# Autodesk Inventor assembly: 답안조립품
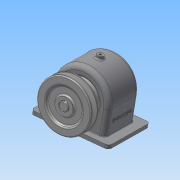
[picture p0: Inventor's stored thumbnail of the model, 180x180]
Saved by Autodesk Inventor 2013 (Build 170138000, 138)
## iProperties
Created: 2015-09
Part Number: 답안조립품
Document SubType Name: Assembly
Designer: ST3
Author: ST3
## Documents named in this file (14)
- C:\Users\ST3\Desktop\450907V1005\답안조립품.iam
- C:\Users\ST3\Desktop\450907V1005\V-벨트풀리.ipt
- C:\Users\ST3\Desktop\450907V1005\뒤커버.ipt
- C:\Users\ST3\Desktop\450907V1005\멈춤나사 - M4x10.ipt
- C:\Users\ST3\Desktop\450907V1005\베어링 6203.ipt
- C:\Users\ST3\Desktop\450907V1005\본체.ipt
- C:\Users\ST3\Desktop\450907V1005\볼트 M3 x 8.ipt
- C:\Users\ST3\Desktop\450907V1005\볼트 M3 x 10.ipt
- C:\Users\ST3\Desktop\450907V1005\스퍼기어.ipt
- C:\Users\ST3\Desktop\450907V1005\앞커버.ipt
- C:\Users\ST3\Desktop\450907V1005\오일 실 17 32 8.ipt
- C:\Users\ST3\Desktop\450907V1005\축.ipt
- C:\Users\ST3\Desktop\450907V1005\키 - 5 x 5 x 18.ipt
- C:\Users\ST3\Desktop\450907V1005\키 - 6 x 6 x 22.ipt
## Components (9 placed, 3 different names)
1. V-벨트풀리:1
2. ISO 4762 M3 x 8:1
3. ISO 4762 M3 x 10:1
4. ISO 4762 M3 x 10:2
5. ISO 4762 M3 x 10:3
6. ISO 4762 M3 x 10:4
7. ISO 4762 M3 x 8:2
8. ISO 4762 M3 x 8:3
9. ISO 4762 M3 x 8:4
